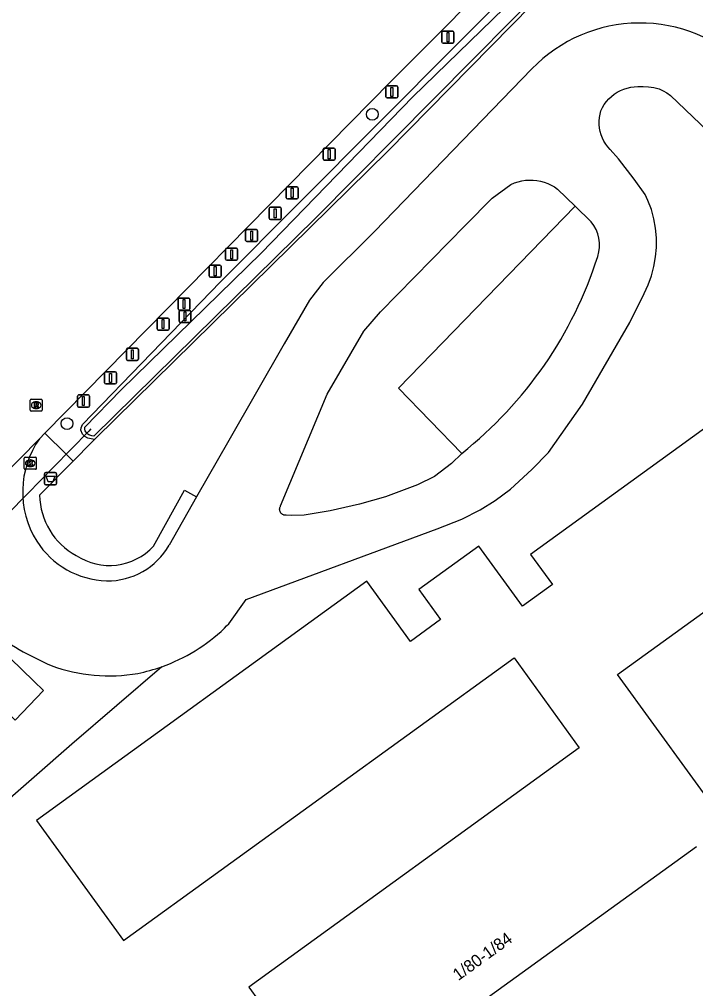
# Model space of a CAD drawing. Extents: x 162791 to 163827, y 385795 to 386523.
# Drawn here: x 163031.1 to 163087.1, y 386278.4 to 386358.7 of the extents above; entities that cross this region are included whole.
import ezdxf

# ---------------------------------------------------------------- set-up
doc = ezdxf.new("R2010")
doc.units = 0
for name, color, linetype in [('IMGEO_Afsluitpaal', 7, 'Continuous'), ('IMGEO_Afvalbak', 7, 'Continuous'), ('IMGEO_Boom', 7, 'Continuous'), ('IMGEO_Duiker', 7, 'Continuous'), ('IMGEO_Erf', 7, 'Continuous'), ('IMGEO_Groenvoorziening', 7, 'Continuous'), ('IMGEO_Kolk', 7, 'Continuous'), ('IMGEO_Pand', 7, 'Continuous'), ('IMGEO_Pand_nummerreeks', 7, 'Continuous'), ('IMGEO_Parkeervlak_gesloten', 7, 'Continuous'), ('IMGEO_Rijbaan_lokaal_open', 7, 'Continuous'), ('IMGEO_Rioolput', 7, 'Continuous'), ('IMGEO_Verkeersbordpaal', 7, 'Continuous'), ('IMGEO_Voetpad_open', 7, 'Continuous'), ('IMGEO_Waterloop', 7, 'Continuous'), ('IMGEO_Woonerf_gesloten', 7, 'Continuous'), ('IMGEO_Woonerf_open', 7, 'Continuous')]:
    doc.layers.add(name, color=color, linetype=linetype)

msp = doc.modelspace()

# ---------------------------------------------------------------- linework, layer by layer
at = {"layer": 'IMGEO_Afsluitpaal'}
for p, q in [((163066.129, 386356.798), (163066.129, 386357.598)), ((163066.129, 386357.598), (163066.129, 386356.798)), ((163066.229, 386357.698), (163067.019, 386357.698)), ((163067.019, 386357.698), (163066.229, 386357.698)), ((163067.119, 386357.598), (163067.119, 386356.798)), ((163067.119, 386356.798), (163067.119, 386357.598)), ((163067.019, 386356.698), (163066.229, 386356.698)), ((163066.229, 386356.698), (163067.019, 386356.698)), ((163061.585, 386353.165), (163062.375, 386353.165)), ((163062.375, 386353.165), (163061.585, 386353.165)), ((163061.485, 386352.265), (163061.485, 386353.065)), ((163061.485, 386353.065), (163061.485, 386352.265)), ((163062.475, 386353.065), (163062.475, 386352.265)), ((163062.475, 386352.265), (163062.475, 386353.065)), ((163062.375, 386352.165), (163061.585, 386352.165)), ((163061.585, 386352.165), (163062.375, 386352.165)), ((163056.289, 386347.105), (163056.289, 386347.905)), ((163056.289, 386347.905), (163056.289, 386347.105)), ((163056.389, 386348.005), (163057.179, 386348.005)), ((163057.179, 386348.005), (163056.389, 386348.005)), ((163057.279, 386347.905), (163057.279, 386347.105)), ((163057.279, 386347.105), (163057.279, 386347.905)), ((163057.179, 386347.005), (163056.389, 386347.005)), ((163056.389, 386347.005), (163057.179, 386347.005)), ((163053.23, 386343.899), (163053.23, 386344.699)), ((163053.23, 386344.699), (163053.23, 386343.899)), ((163053.33, 386344.799), (163054.12, 386344.799)), ((163054.12, 386344.799), (163053.33, 386344.799)), ((163054.22, 386344.699), (163054.22, 386343.899)), ((163054.22, 386343.899), (163054.22, 386344.699)), ((163054.12, 386343.799), (163053.33, 386343.799)), ((163053.33, 386343.799), (163054.12, 386343.799)), ((163051.829, 386342.203), (163051.829, 386343.003)), ((163051.829, 386343.003), (163051.829, 386342.203)), ((163051.929, 386343.103), (163052.719, 386343.103)), ((163052.719, 386343.103), (163051.929, 386343.103)), ((163052.819, 386343.003), (163052.819, 386342.203)), ((163052.819, 386342.203), (163052.819, 386343.003)), ((163052.719, 386342.103), (163051.929, 386342.103)), ((163051.929, 386342.103), (163052.719, 386342.103)), ((163049.876, 386340.361), (163049.876, 386341.161)), ((163049.876, 386341.161), (163049.876, 386340.361)), ((163049.976, 386341.261), (163050.766, 386341.261)), ((163050.766, 386341.261), (163049.976, 386341.261)), ((163050.866, 386341.161), (163050.866, 386340.361)), ((163050.866, 386340.361), (163050.866, 386341.161)), ((163050.766, 386340.261), (163049.976, 386340.261)), ((163049.976, 386340.261), (163050.766, 386340.261)), ((163048.218, 386338.813), (163048.218, 386339.613)), ((163048.218, 386339.613), (163048.218, 386338.813)), ((163048.318, 386339.713), (163049.108, 386339.713)), ((163049.108, 386339.713), (163048.318, 386339.713)), ((163049.208, 386339.613), (163049.208, 386338.813)), ((163049.208, 386338.813), (163049.208, 386339.613)), ((163049.108, 386338.713), (163048.318, 386338.713)), ((163048.318, 386338.713), (163049.108, 386338.713)), ((163046.854, 386337.412), (163046.854, 386338.212)), ((163046.854, 386338.212), (163046.854, 386337.412)), ((163046.954, 386338.312), (163047.744, 386338.312)), ((163047.744, 386338.312), (163046.954, 386338.312)), ((163047.844, 386338.212), (163047.844, 386337.412)), ((163047.844, 386337.412), (163047.844, 386338.212)), ((163047.744, 386337.312), (163046.954, 386337.312)), ((163046.954, 386337.312), (163047.744, 386337.312)), ((163044.274, 386334.685), (163044.274, 386335.485)), ((163044.274, 386335.485), (163044.274, 386334.685)), ((163044.374, 386335.585), (163045.164, 386335.585)), ((163045.164, 386335.585), (163044.374, 386335.585)), ((163045.264, 386335.485), (163045.264, 386334.685)), ((163045.264, 386334.685), (163045.264, 386335.485)), ((163042.542, 386333.027), (163042.542, 386333.827)), ((163042.542, 386333.827), (163042.542, 386333.027)), ((163042.642, 386333.927), (163043.432, 386333.927)), ((163043.432, 386333.927), (163042.642, 386333.927)), ((163043.532, 386333.827), (163043.532, 386333.027)), ((163043.532, 386333.027), (163043.532, 386333.827)), ((163045.164, 386334.585), (163044.374, 386334.585)), ((163044.374, 386334.585), (163045.164, 386334.585)), ((163043.432, 386332.927), (163042.642, 386332.927)), ((163042.642, 386332.927), (163043.432, 386332.927)), ((163040.099, 386331.42), (163040.889, 386331.42)), ((163040.889, 386331.42), (163040.099, 386331.42)), ((163039.999, 386330.52), (163039.999, 386331.32)), ((163039.999, 386331.32), (163039.999, 386330.52)), ((163040.989, 386331.32), (163040.989, 386330.52)), ((163040.989, 386330.52), (163040.989, 386331.32)), ((163040.889, 386330.42), (163040.099, 386330.42)), ((163040.099, 386330.42), (163040.889, 386330.42)), ((163038.193, 386328.567), (163038.193, 386329.367)), ((163038.193, 386329.367), (163038.193, 386328.567)), ((163038.293, 386329.467), (163039.083, 386329.467)), ((163039.083, 386329.467), (163038.293, 386329.467)), ((163039.183, 386329.367), (163039.183, 386328.567)), ((163039.183, 386328.567), (163039.183, 386329.367)), ((163039.083, 386328.467), (163038.293, 386328.467)), ((163038.293, 386328.467), (163039.083, 386328.467)), ((163035.945, 386326.651), (163035.945, 386327.451)), ((163035.945, 386327.451), (163035.945, 386326.651)), ((163036.045, 386327.551), (163036.835, 386327.551)), ((163036.835, 386327.551), (163036.045, 386327.551)), ((163036.935, 386327.451), (163036.935, 386326.651)), ((163036.935, 386326.651), (163036.935, 386327.451)), ((163036.835, 386326.551), (163036.045, 386326.551)), ((163036.045, 386326.551), (163036.835, 386326.551))]:
    msp.add_line(p, q, dxfattribs=at)
for points in [[(163066.549, 386357.573), (163066.699, 386357.573), (163066.699, 386356.823), (163066.549, 386356.823), (163066.549, 386357.573)], [(163061.905, 386353.04), (163062.055, 386353.04), (163062.055, 386352.29), (163061.905, 386352.29), (163061.905, 386353.04)], [(163056.709, 386347.88), (163056.859, 386347.88), (163056.859, 386347.13), (163056.709, 386347.13), (163056.709, 386347.88)], [(163053.65, 386344.674), (163053.8, 386344.674), (163053.8, 386343.924), (163053.65, 386343.924), (163053.65, 386344.674)], [(163052.249, 386342.978), (163052.399, 386342.978), (163052.399, 386342.228), (163052.249, 386342.228), (163052.249, 386342.978)], [(163050.296, 386341.136), (163050.446, 386341.136), (163050.446, 386340.386), (163050.296, 386340.386), (163050.296, 386341.136)], [(163048.638, 386339.588), (163048.788, 386339.588), (163048.788, 386338.838), (163048.638, 386338.838), (163048.638, 386339.588)], [(163047.274, 386338.187), (163047.424, 386338.187), (163047.424, 386337.437), (163047.274, 386337.437), (163047.274, 386338.187)], [(163044.694, 386335.46), (163044.844, 386335.46), (163044.844, 386334.71), (163044.694, 386334.71), (163044.694, 386335.46)], [(163042.962, 386333.802), (163043.112, 386333.802), (163043.112, 386333.052), (163042.962, 386333.052), (163042.962, 386333.802)], [(163040.419, 386331.295), (163040.569, 386331.295), (163040.569, 386330.545), (163040.419, 386330.545), (163040.419, 386331.295)], [(163038.613, 386329.342), (163038.763, 386329.342), (163038.763, 386328.592), (163038.613, 386328.592), (163038.613, 386329.342)], [(163036.365, 386327.426), (163036.515, 386327.426), (163036.515, 386326.676), (163036.365, 386326.676), (163036.365, 386327.426)]]:
    msp.add_lwpolyline(points, dxfattribs=at)
for centre, start, end in [((163066.229, 386357.598), 90, 180), ((163066.229, 386357.598), 90, 180), ((163067.019, 386357.598), 0, 90), ((163067.019, 386357.598), 360, 90), ((163066.229, 386356.798), 180, 270), ((163066.229, 386356.798), 180, 270), ((163067.019, 386356.798), 270, 0), ((163067.019, 386356.798), 270, 0), ((163061.585, 386353.065), 90, 180), ((163061.585, 386353.065), 90, 180), ((163062.375, 386353.065), 0, 90), ((163062.375, 386353.065), 360, 90), ((163061.585, 386352.265), 180, 270), ((163061.585, 386352.265), 180, 270), ((163062.375, 386352.265), 270, 0), ((163062.375, 386352.265), 270, 0), ((163056.389, 386347.905), 90, 180), ((163056.389, 386347.905), 90, 180), ((163057.179, 386347.905), 0, 90), ((163057.179, 386347.905), 360, 90), ((163056.389, 386347.105), 180, 270), ((163056.389, 386347.105), 180, 270), ((163057.179, 386347.105), 270, 0), ((163057.179, 386347.105), 270, 0), ((163053.33, 386344.699), 90, 180), ((163053.33, 386344.699), 90, 180), ((163054.12, 386344.699), 0, 90), ((163054.12, 386344.699), 360, 90), ((163053.33, 386343.899), 180, 270), ((163053.33, 386343.899), 180, 270), ((163054.12, 386343.899), 270, 0), ((163054.12, 386343.899), 270, 0), ((163051.929, 386343.003), 90, 180), ((163051.929, 386343.003), 90, 180), ((163052.719, 386343.003), 0, 90), ((163052.719, 386343.003), 360, 90), ((163051.929, 386342.203), 180, 270), ((163051.929, 386342.203), 180, 270), ((163052.719, 386342.203), 270, 0), ((163052.719, 386342.203), 270, 0), ((163049.976, 386341.161), 90, 180), ((163049.976, 386341.161), 90, 180), ((163050.766, 386341.161), 0, 90), ((163050.766, 386341.161), 360, 90), ((163049.976, 386340.361), 180, 270), ((163049.976, 386340.361), 180, 270), ((163050.766, 386340.361), 270, 0), ((163050.766, 386340.361), 270, 0), ((163048.318, 386339.613), 90, 180), ((163048.318, 386339.613), 90, 180), ((163049.108, 386339.613), 0, 90), ((163049.108, 386339.613), 360, 90), ((163048.318, 386338.813), 180, 270), ((163048.318, 386338.813), 180, 270), ((163049.108, 386338.813), 270, 0), ((163049.108, 386338.813), 270, 0), ((163046.954, 386338.212), 90, 180), ((163046.954, 386338.212), 90, 180), ((163047.744, 386338.212), 0, 90), ((163047.744, 386338.212), 360, 90), ((163046.954, 386337.412), 180, 270), ((163046.954, 386337.412), 180, 270), ((163047.744, 386337.412), 270, 0), ((163047.744, 386337.412), 270, 0), ((163044.374, 386335.485), 90, 180), ((163044.374, 386335.485), 90, 180), ((163045.164, 386335.485), 0, 90), ((163045.164, 386335.485), 360, 90), ((163044.374, 386334.685), 180, 270), ((163044.374, 386334.685), 180, 270), ((163045.164, 386334.685), 270, 0), ((163045.164, 386334.685), 270, 0), ((163042.642, 386333.827), 90, 180), ((163042.642, 386333.827), 90, 180), ((163043.432, 386333.827), 0, 90), ((163043.432, 386333.827), 360, 90), ((163042.642, 386333.027), 180, 270), ((163042.642, 386333.027), 180, 270), ((163043.432, 386333.027), 270, 0), ((163043.432, 386333.027), 270, 0), ((163040.099, 386331.32), 90, 180), ((163040.099, 386331.32), 90, 180), ((163040.889, 386331.32), 0, 90), ((163040.889, 386331.32), 360, 90), ((163040.099, 386330.52), 180, 270), ((163040.099, 386330.52), 180, 270), ((163040.889, 386330.52), 270, 0), ((163040.889, 386330.52), 270, 0), ((163038.293, 386329.367), 90, 180), ((163038.293, 386329.367), 90, 180), ((163039.083, 386329.367), 0, 90), ((163039.083, 386329.367), 360, 90), ((163038.293, 386328.567), 180, 270), ((163038.293, 386328.567), 180, 270), ((163039.083, 386328.567), 270, 0), ((163039.083, 386328.567), 270, 0), ((163036.045, 386327.451), 90, 180), ((163036.045, 386327.451), 90, 180), ((163036.835, 386327.451), 0, 90), ((163036.835, 386327.451), 360, 90), ((163036.045, 386326.651), 180, 270), ((163036.045, 386326.651), 180, 270), ((163036.835, 386326.651), 270, 0), ((163036.835, 386326.651), 270, 0)]:
    msp.add_arc(centre, 0.1, start, end, dxfattribs=at)
at = {"layer": 'IMGEO_Afvalbak'}
for p, q in [((163033.225, 386320.218), (163033.225, 386321.018)), ((163033.225, 386321.018), (163033.225, 386320.218)), ((163033.325, 386321.118), (163034.115, 386321.118)), ((163034.115, 386321.118), (163033.325, 386321.118)), ((163034.215, 386321.018), (163034.215, 386320.218)), ((163034.215, 386320.218), (163034.215, 386321.018)), ((163034.115, 386320.118), (163033.325, 386320.118)), ((163033.325, 386320.118), (163034.115, 386320.118))]:
    msp.add_line(p, q, dxfattribs=at)
msp.add_lwpolyline([(163033.368, 386320.832), (163034.072, 386320.832), (163033.923, 386320.362), (163033.517, 386320.362), (163033.368, 386320.832)], dxfattribs=at)
for centre, start, end in [((163033.325, 386321.018), 90, 180), ((163033.325, 386321.018), 90, 180), ((163034.115, 386321.018), 0, 90), ((163034.115, 386321.018), 360, 90), ((163033.325, 386320.218), 180, 270), ((163033.325, 386320.218), 180, 270), ((163034.115, 386320.218), 270, 0), ((163034.115, 386320.218), 270, 0)]:
    msp.add_arc(centre, 0.1, start, end, dxfattribs=at)
at = {"layer": 'IMGEO_Boom'}
for centre in [(163060.359, 386350.805), (163035.084, 386325.182)]:
    msp.add_circle(centre, 0.489, dxfattribs=at)
at = {"layer": 'IMGEO_Duiker'}
for points in [[(163036.891, 386324.56), (163033.956, 386321.564)], [(163037.069, 386324.741), (163036.891, 386324.56)], [(163033.956, 386321.564), (163031.803, 386319.366)], [(163031.803, 386319.366), (163030.15, 386317.68)]]:
    msp.add_lwpolyline(points, dxfattribs=at)
at = {"layer": 'IMGEO_Erf'}
msp.add_lwpolyline([(163137.51, 386422.154), (163124.272, 386408.886), (163117.535, 386402.875), (163088.92, 386375.511), (163061.654, 386347.743), (163037.466, 386323.975), (163037.353, 386323.86)], dxfattribs=at)
at = {"layer": 'IMGEO_Groenvoorziening'}
for points in [[(163037.353, 386323.86), (163037.078, 386323.909), (163036.814, 386323.985), (163036.557, 386324.124), (163036.51, 386324.171), (163036.363, 386324.317), (163036.233, 386324.633), (163036.258, 386324.83), (163036.366, 386325.094), (163047.781, 386336.916), (163113.115, 386402.594), (163135.492, 386424.574)], [(163037.353, 386323.86), (163037.126, 386323.629), (163035.605, 386322.08)]]:
    msp.add_lwpolyline(points, dxfattribs=at)
at = {"layer": 'IMGEO_Kolk'}
for p, q in [((163031.542, 386321.466), (163031.542, 386322.318)), ((163031.617, 386322.392), (163032.469, 386322.392)), ((163032.03, 386322.172), (163032.055, 386322.172)), ((163032.543, 386322.318), (163032.543, 386321.466)), ((163032.469, 386321.392), (163031.617, 386321.392)), ((163032.053, 386321.612), (163032.028, 386321.612))]:
    msp.add_line(p, q, dxfattribs=at)
for points in [[(163031.542, 386321.466), (163031.542, 386322.318)], [(163031.617, 386322.392), (163032.469, 386322.392)], [(163031.863, 386322.092), (163031.986, 386322.092), (163031.986, 386321.941), (163032.116, 386322.092), (163032.28, 386322.092), (163032.134, 386321.941), (163032.287, 386321.692), (163032.135, 386321.692), (163032.05, 386321.856), (163031.986, 386321.789), (163031.986, 386321.692), (163031.863, 386321.692), (163031.863, 386322.092)], [(163032.543, 386322.318), (163032.543, 386321.466)], [(163032.469, 386321.392), (163031.617, 386321.392)]]:
    msp.add_lwpolyline(points, dxfattribs=at)
for centre, start, end in [((163031.619, 386322.316), 91.55205, 178.44795), ((163031.619, 386322.316), 91.55205, 178.44795), ((163032.467, 386322.316), 1.55205, 88.44795), ((163032.467, 386322.316), 1.55205, 88.44795), ((163031.619, 386321.468), 181.55205, 268.44795), ((163031.619, 386321.468), 181.55205, 268.44795), ((163032.467, 386321.468), 271.55205, 358.44795), ((163032.467, 386321.468), 271.55205, 358.44795)]:
    msp.add_arc(centre, 0.0765, start, end, dxfattribs=at)
for centre, major_axis, ratio, start_param, end_param in [((163032.029, 386321.892), (-0.387, 0.002), 0.722429, 4.712389, 7.853982), ((163032.054, 386321.892), (-0.39, 0.002), 0.717154, 1.570796, 4.712389)]:
    msp.add_ellipse(centre, major_axis=major_axis, ratio=ratio, start_param=start_param, end_param=end_param, dxfattribs=at)
at = {"layer": 'IMGEO_Pand'}
for points in [[(163090.885, 386326.947), (163073.472, 386314.341), (163075.273, 386311.854), (163072.785, 386310.053), (163069.183, 386315.028), (163064.208, 386311.426), (163066.009, 386308.939), (163063.522, 386307.138), (163059.92, 386312.113), (163032.557, 386292.304), (163039.76, 386282.353), (163072.098, 386305.764), (163077.501, 386298.302), (163050.138, 386278.492), (163057.341, 386268.542), (163087.192, 386290.152)], [(163089.68, 386291.953), (163080.675, 386304.391), (163098.088, 386316.997)]]:
    msp.add_lwpolyline(points, dxfattribs=at)
at = {"layer": 'IMGEO_Parkeervlak_gesloten'}
for points in [[(163067.774, 386322.714), (163062.517, 386328.123), (163077.161, 386343.197)], [(163077.161, 386343.197), (163078.487, 386341.899)]]:
    msp.add_lwpolyline(points, dxfattribs=at)
for centre, radius, start, end in [((163076.12, 386339.97), 3.054, 342.05744, 39.17704), ((163046.611, 386349.345), 34.016, 308.47319, 342.34568)]:
    msp.add_arc(centre, radius, start, end, dxfattribs=at)
at = {"layer": 'IMGEO_Rijbaan_lokaal_open'}
for points in [[(163033.253, 386324.389), (163061.911, 386353.554), (163072.515, 386364.212), (163089.388, 386381.287), (163102.912, 386395.058), (163111.751, 386404.009), (163120.635, 386413.08), (163132.802, 386425.418)], [(163032.796, 386323.924), (163033.253, 386324.389)], [(163018.251, 386309.139), (163024.508, 386315.489), (163032.796, 386323.924)]]:
    msp.add_lwpolyline(points, dxfattribs=at)
at = {"layer": 'IMGEO_Rioolput'}
for p, q in [((163032.031, 386326.28), (163032.031, 386327.132)), ((163032.106, 386327.206), (163032.958, 386327.206)), ((163032.519, 386326.986), (163032.544, 386326.986)), ((163033.032, 386327.132), (163033.032, 386326.28)), ((163032.958, 386326.206), (163032.106, 386326.206)), ((163032.542, 386326.426), (163032.517, 386326.426))]:
    msp.add_line(p, q, dxfattribs=at)
for points in [[(163032.031, 386326.28), (163032.031, 386327.132)], [(163032.106, 386327.206), (163032.958, 386327.206)], [(163032.62, 386326.904), (163032.368, 386326.906), (163032.368, 386326.506)], [(163032.368, 386326.506), (163032.492, 386326.506), (163032.492, 386326.668), (163032.503, 386326.668)], [(163032.546, 386326.825), (163032.492, 386326.825), (163032.492, 386326.744)], [(163032.492, 386326.744), (163032.544, 386326.744)], [(163032.55, 386326.639), (163032.621, 386326.506), (163032.761, 386326.506), (163032.696, 386326.632)], [(163033.032, 386327.132), (163033.032, 386326.28)], [(163032.958, 386326.206), (163032.106, 386326.206)]]:
    msp.add_lwpolyline(points, dxfattribs=at)
for centre, radius, start, end in [((163032.108, 386327.13), 0.0765, 91.55205, 178.44795), ((163032.108, 386327.13), 0.0765, 91.55205, 178.44795), ((163032.502, 386326.615), 0.0533, 26.02933, 88.69889), ((163032.528, 386326.933), 0.19, 274.7715, 282.96867), ((163032.552, 386326.729), 0.0964, 77.00612, 93.18647), ((163032.566, 386326.786), 0.0378, 276.66336, 79.67722), ((163032.619, 386326.794), 0.109, 350.36119, 89.41601), ((163032.617, 386326.794), 0.112, 277.58423, 350.98172), ((163032.601, 386326.579), 0.108, 29.51342, 73.79051), ((163032.956, 386327.13), 0.0765, 1.55205, 88.44795), ((163032.956, 386327.13), 0.0765, 1.55205, 88.44795), ((163032.108, 386326.282), 0.0765, 181.55205, 268.44795), ((163032.108, 386326.282), 0.0765, 181.55205, 268.44795), ((163032.956, 386326.282), 0.0765, 271.55205, 358.44795), ((163032.956, 386326.282), 0.0765, 271.55205, 358.44795)]:
    msp.add_arc(centre, radius, start, end, dxfattribs=at)
for centre, major_axis, ratio, start_param, end_param in [((163032.518, 386326.706), (-0.387, 0.002), 0.722429, 4.712389, 7.853982), ((163032.543, 386326.706), (-0.39, 0.002), 0.717154, 1.570796, 4.712389)]:
    msp.add_ellipse(centre, major_axis=major_axis, ratio=ratio, start_param=start_param, end_param=end_param, dxfattribs=at)
at = {"layer": 'IMGEO_Verkeersbordpaal'}
for p, q in [((163044.357, 386333.658), (163044.357, 386334.458)), ((163044.357, 386334.458), (163044.357, 386333.658)), ((163044.457, 386334.558), (163045.247, 386334.558)), ((163045.247, 386334.558), (163044.457, 386334.558)), ((163045.347, 386334.458), (163045.347, 386333.658)), ((163045.347, 386333.658), (163045.347, 386334.458)), ((163045.247, 386333.558), (163044.457, 386333.558)), ((163044.457, 386333.558), (163045.247, 386333.558))]:
    msp.add_line(p, q, dxfattribs=at)
msp.add_lwpolyline([(163044.777, 386334.433), (163044.927, 386334.433), (163044.927, 386333.683), (163044.777, 386333.683), (163044.777, 386334.433)], dxfattribs=at)
for centre, start, end in [((163044.457, 386334.458), 90, 180), ((163044.457, 386334.458), 90, 180), ((163045.247, 386334.458), 0, 90), ((163045.247, 386334.458), 360, 90), ((163044.457, 386333.658), 180, 270), ((163044.457, 386333.658), 180, 270), ((163045.247, 386333.658), 270, 0), ((163045.247, 386333.658), 270, 0)]:
    msp.add_arc(centre, 0.1, start, end, dxfattribs=at)
at = {"layer": 'IMGEO_Voetpad_open'}
for points in [[(163033.253, 386324.389), (163035.022, 386322.652), (163035.605, 386322.08)], [(163035.605, 386322.08), (163032.817, 386319.24)], [(163042.256, 386315.029), (163044.092, 386318.357), (163044.817, 386319.669), (163045.817, 386319.118)], [(163045.817, 386319.118), (163043.529, 386315.101)]]:
    msp.add_lwpolyline(points, dxfattribs=at)
for centre, radius, start, end in [((163039.12, 386319.514), 7.71, 145.113, 211.91687), ((163038.619, 386319.344), 5.802, 181.03032, 241.35555), ((163038.565, 386319.252), 7.1, 212.49266, 268.35733), ((163038.588, 386318.427), 5, 236.61609, 317.18771), ((163038.478, 386317.956), 5.802, 268.84424, 330.52606)]:
    msp.add_arc(centre, radius, start, end, dxfattribs=at)
at = {"layer": 'IMGEO_Waterloop'}
msp.add_lwpolyline([(163075.167, 386361.921), (163055.68, 386342.225), (163037.292, 386324.152), (163037.127, 386324.178), (163036.896, 386324.251), (163036.812, 386324.299), (163036.714, 386324.38), (163036.583, 386324.578), (163036.562, 386324.716), (163036.569, 386324.887), (163039.567, 386327.975), (163051.161, 386339.298), (163063.707, 386352.262), (163076.93, 386365.133)], dxfattribs=at)
at = {"layer": 'IMGEO_Woonerf_gesloten'}
for points in [[(163073.582, 386354.585), (163060.531, 386341.104), (163056.284, 386336.88), (163055.171, 386335.397), (163053.06, 386331.777), (163048.478, 386323.791), (163045.817, 386319.118)], [(163048.119, 386308.226), (163048.302, 386308.411), (163048.49, 386308.591), (163049.905, 386310.618), (163065.729, 386316.452), (163067.764, 386317.27), (163069.281, 386318.036), (163070.544, 386318.822), (163071.81, 386319.75), (163073.566, 386321.375), (163074.937, 386322.791), (163077.77, 386326.804), (163081.679, 386333.561), (163082.863, 386335.968), (163083.202, 386336.689), (163083.475, 386337.437), (163083.682, 386338.206), (163083.82, 386338.99), (163083.889, 386339.783), (163083.888, 386340.58), (163083.816, 386341.373), (163083.675, 386342.156), (163083.466, 386342.925), (163083.189, 386343.671), (163082.961, 386344.167), (163082.05, 386345.423), (163080.741, 386347.105), (163080.056, 386347.884), (163079.865, 386348.101), (163079.694, 386348.334), (163079.545, 386348.581), (163079.417, 386348.841), (163079.314, 386349.11), (163079.234, 386349.388), (163079.18, 386349.672), (163079.15, 386349.959), (163079.146, 386350.248), (163079.168, 386350.536), (163079.215, 386350.821), (163079.287, 386351.101), (163079.418, 386351.368), (163079.573, 386351.623), (163079.75, 386351.862), (163079.948, 386352.085), (163080.164, 386352.29), (163080.398, 386352.474), (163080.648, 386352.637), (163080.911, 386352.777), (163081.185, 386352.893), (163081.469, 386352.984), (163081.759, 386353.05), (163082.055, 386353.089), (163082.352, 386353.102), (163082.795, 386353.116), (163083.238, 386353.09), (163083.677, 386353.025), (163084.108, 386352.92), (163084.435, 386352.756), (163084.752, 386352.575), (163085.059, 386352.377), (163094.279, 386343.557)], [(163067.774, 386322.714), (163066.916, 386321.884), (163065.511, 386320.809), (163064.111, 386320.098), (163061.441, 386319.124), (163059.309, 386318.499), (163056.865, 386317.958), (163054.728, 386317.603), (163053.705, 386317.559), (163053.225, 386317.581), (163053.18, 386317.581), (163053.136, 386317.585), (163053.092, 386317.592), (163053.049, 386317.604), (163053.007, 386317.619), (163052.967, 386317.637), (163052.928, 386317.659), (163052.892, 386317.685), (163052.858, 386317.713), (163052.826, 386317.744), (163052.797, 386317.778), (163052.772, 386317.815), (163052.749, 386317.853), (163052.73, 386317.893), (163052.715, 386317.935), (163052.703, 386317.978), (163052.695, 386318.022), (163052.691, 386318.066), (163052.691, 386318.111), (163052.695, 386318.155), (163052.702, 386318.199), (163052.714, 386318.242), (163052.729, 386318.284), (163052.748, 386318.324), (163052.77, 386318.362), (163056.626, 386327.613), (163059.668, 386332.827), (163061.042, 386334.438), (163068.086, 386341.616), (163070.284, 386343.855), (163071.843, 386344.99), (163072.13, 386345.116), (163072.428, 386345.217), (163072.733, 386345.292), (163073.043, 386345.341), (163073.356, 386345.364), (163073.671, 386345.359), (163073.983, 386345.328), (163074.292, 386345.27), (163074.595, 386345.186), (163074.889, 386345.077), (163075.173, 386344.943), (163075.445, 386344.785), (163075.702, 386344.605), (163077.161, 386343.197)]]:
    msp.add_lwpolyline(points, dxfattribs=at)
for centre, radius, start, end in [((163082.519, 386345.935), 12.437, 45.03507, 135.9346), ((163037.959, 386318.926), 14.755, 289.67072, 313.51719), ((163044.291, 386329.223), 26.288, 233.49573, 246.42881), ((163038.592, 386318.324), 14.046, 249.96258, 279.686), ((163037.929, 386319.027), 14.86, 281.74922, 289.64954)]:
    msp.add_arc(centre, radius, start, end, dxfattribs=at)
at = {"layer": 'IMGEO_Woonerf_open'}
for points in [[(163026.459, 386309.437), (163027.447, 386308.568), (163032.342, 386303.852), (163033.149, 386303.075), (163030.783, 386300.619), (163029.975, 386301.398), (163028.087, 386299.438)], [(163042.926, 386305.032), (163035.489, 386298.618), (163029.009, 386292.968), (163026.247, 386290.307), (163022.573, 386293.803)]]:
    msp.add_lwpolyline(points, dxfattribs=at)

# ---------------------------------------------------------------- texts
at = {"layer": 'IMGEO_Pand_nummerreeks'}
msp.add_text('1/80-1/84', height=1, rotation=35.93591, dxfattribs=at).set_placement((163067.477, 386278.978))

doc.saveas('drawing.dxf')
